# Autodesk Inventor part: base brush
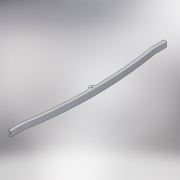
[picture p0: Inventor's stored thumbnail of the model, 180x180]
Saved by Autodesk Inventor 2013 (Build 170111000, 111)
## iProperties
Shininess: 20.0
Length Units: 11269
Angle Units: 11279
Time Units: 11290
Mass Units: 11283
Length Display Precision: 3
Angle Display Precision: 2
Created: 2002-03
Part Number: base brush
Document SubType Name: Modeling
Designer: =<Author>
Density: 1 g/cm^3
Material: Generic
Description: =<Part Number>
Density: 0.0
Volumn: 0.0
Area: 0.0
PropertySet Name: Model Information
Control State: 0
Master: False
Checked Out: True
Last Check In Date: 2008-10-15
Checked Out Date: 2008-10-15
Author: LAlexey
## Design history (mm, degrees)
sketch "Sketch1"
  geometry: L1 (0, -266.579)-(0, -291); L2 (0, -291)-(5, -291); L3 (5, -267)-(5, -291); L4 (5, -5)-(5, 19); L5 (0, 19)-(5, 19); L6 (0, 19)-(0, -5.421); L7 (0, -267)-(0, -291); L8 (0, 19)-(0, -5); A1 r 5 centre (11, -136) between (7.643, -132.295) and (7.643, -139.705); A2 r 10 centre (0.928, -147.115) between (10.927, -147.256) and (7.643, -139.705); A3 r 780 centre (-768.992, -136) between (0, -266.579) and (10.927, -147.256); A4 r 785 centre (-768.992, -136) between (5, -267) and (5, -5); A5 r 780 centre (-768.992, -136) between (10.927, -124.744) and (0, -5.421); A6 r 10 centre (0.928, -124.885) between (7.643, -132.295) and (10.927, -124.744)
  constraints: 16 end point, 12 point on circle, 6 centre point, 6 vertical, 2 collinear, 2 concentric, 2 horizontal, 2 tangent, 1 other
  dimensions: "d1" = 310 distance of L4.end L2.end; "d3" = 785 radius of A4; "d5" = 780 radius of A5; "d7" = 5 distance of L4.end L5.start; "d9" = 155 vertical distance of A1.centre L5.start; "d11" = 10 radius of A2; "d13" = 5 radius of A1; "d15" = 6 horizontal distance of A1.centre L4.start
extrude "ExtrusionBlind1" new body sketch "Sketch1" distance "d16" = 12; taper "d17" = 0 deg
sketch "Sketch2"
  geometry: L1 (0, -1)-(155, 0); L2 (0, -1)-(0, -11); L3 (155, -12)-(0, -11); L4 (310, -11)-(155, -12); L5 (310, -1)-(310, -11); L6 (155, 0)-(310, -1); L7 (310, 0)-(310, -12) reference; L8 (285.579, 0)-(166.256, 0) reference
  constraints: 12 end point, 2 parallel, 2 vertical, 1 collinear
  dimensions: "d20" = 10 distance of L5.start L4.start; "d22" = 1 vertical distance of L1.end L5.start; "d24" = 310 distance of L4.start L2.end; "d26" = 155 horizontal distance of L5.start L3.start; "d28" = 155 horizontal distance of L1.start L1.end; "d30" = 1 vertical distance of L3.start L4.start
extrude "ExtrusionThru1" sketch "Sketch2" stored distance "d31" = 0.13; taper "d32" = 0 deg
shell "Shell1" dims "d33" = 1
node "WorkPlane1"
node "WorkPlane2"
sketch "Sketch3"
  geometry: L1 (0, 10)-(0, 0); L2 (-1, 10)-(0, 10); L3 (-1, 0)-(-1, 10); L4 (0, 0)-(-1, 0); L5 (5, 10)-(0, 10) reference; L6 (0, 0)-(5, 0) reference; L7 (0, -1)-(0, 0)
  constraints: 10 end point, 3 collinear, 2 vertical
  dimensions: "d42" = 1 distance of L2.start L5.end
extrude "ExtrusionBlind2" join sketch "Sketch3" distance "d43" = 1; taper "d44" = 0 deg
sketch "Sketch4"
  geometry: L1 (-1, 10)-(-1, 0); L2 (0, 10)-(-1, 10); L3 (0, 0)-(0, 10); L4 (-1, 0)-(0, 0); L5 (0, 11)-(0, 10); L6 (5, 0)-(0, 0) reference; L7 (0, 10)-(5, 10) reference
  constraints: 10 end point, 3 collinear, 2 horizontal, 2 vertical
  dimensions: "d46" = 1 distance of L1.end L6.end
extrude "ExtrusionBlind3" join sketch "Sketch4" distance "d47" = 1; taper "d48" = 0 deg
sketch "Sketch5"
  geometry: 1 further point
hole "Hole1" sketch "Sketch5" at (4.008, 0) diameter "d49" = 3; stored, may be unused: countersink angle "d53" = 60 deg, drill point angle "d55" = 118 deg; dims "d50" = 6, "d51" = 4, "d52" = 2, "d54" = 8
sketch "Sketch6"
  geometry: 1 further point
hole "Hole2" sketch "Sketch6" at (5, 0.006) diameter "d56" = 3; stored, may be unused: countersink angle "d60" = 60 deg, drill point angle "d62" = 118 deg; dims "d57" = 6, "d58" = 4, "d59" = 2, "d61" = 8
body "Solid1"
other parameters: "d2" = 785 (derived), "d6" = 5 (derived), "d8" = 155 (derived), "d12" = 5 (derived), "d14" = 6 (derived), "d18" = 0, "d21" = 1 (derived), "d25" = 155 (derived), "d27" = 155 (derived), "d29" = 1 (derived), "d34" = 0, "d35" = 0, "d36" = 0, "d37" = 0, "d38" = 0, "d39" = -5, "d40" = -5, "d41" = 1 (derived), "d45" = 1 (derived)
